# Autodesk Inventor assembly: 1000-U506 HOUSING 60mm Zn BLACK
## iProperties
Created: 2007-03
Part Number: 1000-U506 HOUSING 60mm Zn BLACK
Document SubType Name: Assembly
Designer: Andy Moles
Translation Standard: STEP AP214IS
File Name: 1000-U504_ASM
Preprocessor: PRO/ENGINEER BY PARAMETRIC TECHNOLOGY CORPORATION, 2003200
Postprocessor: Build: 344b, Release: 11 SP2 - Date: Fri 08/18/2006
Sent Units: MILLIMETERS
Uncertainty: 0.008002179509513001
Author: Andy Moles
